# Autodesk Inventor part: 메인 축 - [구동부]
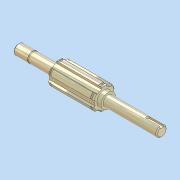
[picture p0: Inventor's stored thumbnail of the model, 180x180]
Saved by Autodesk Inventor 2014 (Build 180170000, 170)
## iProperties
Created: 2012-05
Part Number: 메인 축 - [구동부]
Document SubType Name: 모델링
Designer: SeoGD™
Mass: 21.4461 g
Surface Area: 72.5104 cm^2
Volume: 21.4461 cm^3
Density: 1 g/cm^3
Material: 강철, 연강
Appearance: 강철
변환 표준: STEP AP214IS
파일 이름: C:\Users\SeoGD\Desktop\?쒗뿕\硫붿씤 異?.stp
전처리기: Build: 253, Release: 2010 SP1 - Date: Wed 07/29/2009
전송 단위: 밀리미터
불확실성: 0.01
Author: SeoGD™
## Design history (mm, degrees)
sketch "스케치1"
  geometry: L1 (-69.5, 0)-(69.5, 0); L2 (69.5, 0)-(69.5, 5); L3 (69.5, 5)-(55.5, 5); L4 (55.5, 5)-(55.5, 4.8); L5 (55.5, 4.8)-(54.35, 4.8); L6 (54.35, 4.8)-(54.35, 5); L7 (54.35, 5)-(30.5, 5); L8 (30.5, 5)-(30.5, 9); L9 (30.5, 9)-(-13.5, 9); L10 (-13.5, 9)-(-13.5, 7); L11 (-13.5, 7)-(-17.5, 7); L12 (-17.5, 7)-(-17.5, 5); L13 (-17.5, 5)-(-69.5, 5); L14 (-69.5, 5)-(-69.5, 0); 2 further points
  constraints: 28 end point, 9 parallel, 4 collinear, 2 perpendicular, 1 coincident, 1 horizontal, 1 midpoint
  dimensions: "d2" = 1.15 distance between parallel lines of L6 L4; "d3" = 10 diameter of L3 L1; "d4" = 9.6 diameter of L5 L1; "d6" = 44 distance between parallel lines of L10 L8; "d7" = 4 distance between parallel lines of L12 L10; "d8" = 14 diameter of L11 L1; "d9" = 18 diameter of L9 L1; "d33" = 52 distance from line of L12.end L14; "d37" = 39 distance between parallel lines of L8 L2; "d38" = 14 distance between parallel lines of L2 L4
revolve "회전1" sketch "스케치1" stored, may be unused: angle "d10" = 90 deg
sketch "스케치2"
  geometry: L1 (2.5, 10.712)-(2.5, 8.646); L2 (-2.5, 10.712)-(-2.5, 8.646); A1 r 9 centre (0, 0) between (2.5, 8.646) and (-2.5, 8.646) reference; A2 r 11 centre (0, 0) between (2.5, 10.712) and (-2.5, 10.712); 1 further point
  constraints: 4 end point, 4 point on circle, 2 parallel, 1 centre point, 1 coincident, 1 vertical
  dimensions: "d11" = 22 diameter of A2; "d12" = 5 distance between parallel lines of L1 L2
extrude "돌출1" join sketch "스케치2" stored distance "d13" = 10; taper "d14" = 0 deg
chamfer "모따기1" distance "d15" = 1; stored, may be unused: second distance "d16" = 2, angle "d17" = 45 deg
node "작업 평면1"
node "작업 평면2"
sketch "스케치3"
  geometry: L1 (2.5, 10.712)-(2.5, 10.198); L2 (-2.5, 10.712)-(-2.5, 10.198); A1 r 11 centre (0, 0) between (2.5, 10.712) and (-2.5, 10.712) reference; A2 r 10.5 centre (0, 0) between (2.5, 10.198) and (-2.5, 10.198); 1 further point
  constraints: 4 end point, 2 point on circle, 1 centre point, 1 coincident, 1 parallel, 1 vertical
  dimensions: "d19" = 21 diameter of A2
extrude "돌출2" cut sketch "스케치3" distance "d20" = 1.35; taper "d21" = 0 deg
node "작업 평면3"
sketch "스케치4"
  geometry: L1 (-26, -5)-(-26, 5) reference; L2 (-26, 1.5)-(-12.5, 1.5); L3 (-12.5, -1.5)-(-26, -1.5); A1 r 1.5 centre (-12.5, 0) between (-12.5, -1.5) and (-12.5, 1.5); 2 further points
  constraints: 4 end point, 2 perpendicular, 2 point on circle, 2 point on line, 2 tangent, 1 centre point, 1 horizontal alignment, 1 midpoint
  dimensions: "d25" = 3 distance between parallel lines of L3 L2; "d26" = 15 dimension on A1 L1
extrude "돌출3" cut sketch "스케치4" distance "d27" = 1.8; taper "d28" = 0 deg
chamfer "모따기2" distance "d29" = 1; stored, may be unused: second distance "d30" = 2, angle "d31" = 45 deg
node "솔리드1"
node "솔리드 본체"
node "곡면 본체"
mirror "대칭1"
pattern_circular "원형 패턴1" dims "d23" = 360 deg
node "솔리드2"
other parameters: "d18" = -1.65
